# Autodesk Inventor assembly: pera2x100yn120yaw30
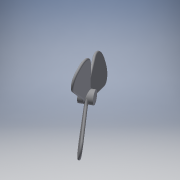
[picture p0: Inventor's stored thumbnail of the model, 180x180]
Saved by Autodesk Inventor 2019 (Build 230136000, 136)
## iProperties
Created: 2020-08
Part Number: pera2x100yn120yaw30
Material: 一般
Document SubType Name: Assembly
Designer: kikut
Author: kikut
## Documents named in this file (2)
- F:\openFOAM\bathrobo\bathrobo05\oversetmeshpera2\CAD\pera2x100yn120yaw30.iam
- F:\openFOAM\bathrobo\bathrobo05\oversetmeshpera2\CAD\pera02.ipt
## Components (1 placed, 1 different names)
1. pera02:1 — 角度:1, メイト:1, メイト:2, メイト:3
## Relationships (4: Mate 3, Angle 1)
- 角度:1 [Angle]: pera02:1
- メイト:1 [Mate]: pera02:1
- メイト:2 [Mate]: pera02:1
- メイト:3 [Mate]: pera02:1
